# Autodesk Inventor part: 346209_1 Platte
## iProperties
Created: 2006-10
Part Number: 346209_1 Platte
Material: St 37-2 K
Description: Platte
Document SubType Name: Modeling
Designer: OSchmidt
Cost Center: 2,093 kg
Authority: 266561 mm^3
Density: 7.85 g/cm^3
SaveDate: 2006-11-06
SaveTime: 22:04
TotalMass: 2,093 kg
TotalVolume: 266561 mm^3
Author: Natti_01
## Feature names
1. Extrusion3
2. Bohrung1 [Hole]
3. Bohrung2 [Hole]
4. Rechteckige Anordnung1 [Rectangular Pattern]
5. Extrusion4
6. Bohrung3 [Hole]
7. Spiegeln1 [Mirror]
